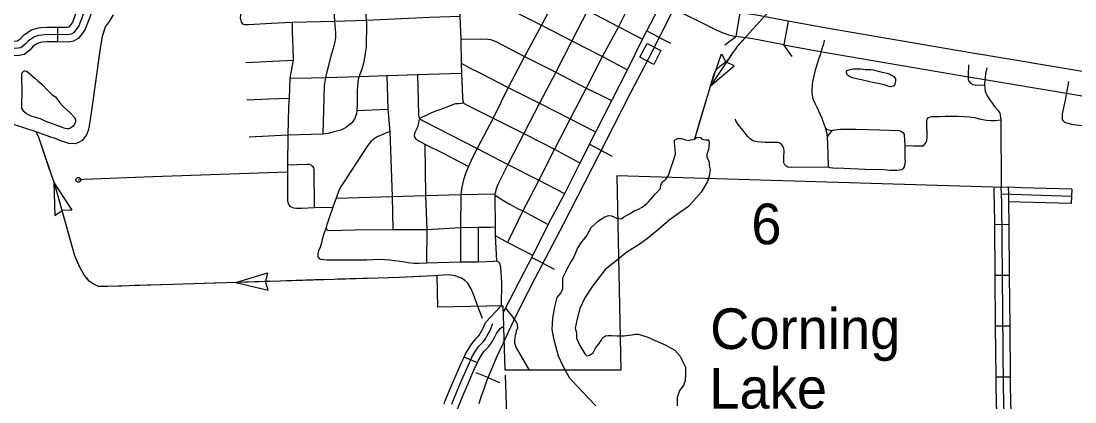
# Model space of a CAD drawing. Extents: x 1164457 to 1439835, y 1590918 to 1773502.
# Drawn here: x 1293538 to 1304504, y 1629674 to 1633633 of the extents above; entities that cross this region are included whole.
import ezdxf

# ---------------------------------------------------------------- set-up
doc = ezdxf.new("R2010")
doc.units = 0
for name, color, linetype in [('Level 10', 7, 'Continuous'), ('Level 15', 7, 'Continuous'), ('Level 32', 7, 'Continuous'), ('Level 33', 7, 'Continuous'), ('Level 34', 7, 'Continuous'), ('Level 35', 7, 'Continuous'), ('Level 37', 7, 'Continuous'), ('Level 4', 7, 'Continuous'), ('Level 40', 7, 'Continuous'), ('Level 43', 7, 'Continuous'), ('Level 45', 7, 'Continuous'), ('Level 5', 7, 'Continuous'), ('Level 6', 7, 'Continuous')]:
    doc.layers.add(name, color=color, linetype=linetype)

msp = doc.modelspace()

# ---------------------------------------------------------------- linework, layer by layer
at = {"layer": 'Level 10'}
for points in [[(1306005, 1632861), (1304458, 1633130), (1303607, 1633270), (1303419, 1633303), (1301918, 1633558), (1301522, 1633633), (1301476, 1633387)], [(1301476, 1633387), (1301874, 1633312), (1303377, 1633056), (1303566, 1633024), (1304416, 1632883), (1305965, 1632615)]]:
    msp.add_lwpolyline(points, dxfattribs=at)
at = {"layer": 'Level 15'}
for points in [[(1300195, 1633840), (1300443, 1633703), (1300612, 1633620), (1300765, 1633544), (1300833, 1633513), (1300904, 1633490), (1300944, 1633479), (1300979, 1633472), (1301022, 1633719)], [(1301522, 1633633), (1301192, 1633695), (1301022, 1633719)], [(1301476, 1633387), (1301151, 1633448), (1300979, 1633472)]]:
    msp.add_lwpolyline(points, dxfattribs=at)
at = {"layer": 'Level 32'}
for p, q in [((1293917, 1633566), (1293916, 1633416)), ((1303820, 1631517), (1303670, 1631516)), ((1303824, 1630989), (1303675, 1630988)), ((1303829, 1630461), (1303679, 1630460)), ((1298286, 1630081), (1298149, 1630141)), ((1303834, 1629933), (1303684, 1629932))]:
    msp.add_line(p, q, dxfattribs=at)
for points in [[(1294219, 1633889), (1294220, 1633849), (1294217, 1633804), (1294200, 1633746), (1294173, 1633672), (1294139, 1633584), (1294111, 1633544), (1294083, 1633512), (1294058, 1633497), (1294023, 1633490), (1293808, 1633492), (1293753, 1633488), (1293721, 1633482), (1293678, 1633469), (1293616, 1633428), (1293578, 1633388), (1293537, 1633356), (1293508, 1633350), (1293465, 1633347)], [(1294294, 1633832), (1294292, 1633791), (1294272, 1633722), (1294243, 1633645), (1294205, 1633549), (1294170, 1633498), (1294132, 1633453), (1294084, 1633425), (1294030, 1633415), (1293916, 1633416)], [(1294144, 1633839), (1294143, 1633816), (1294129, 1633770), (1294103, 1633698), (1294072, 1633619), (1294051, 1633589), (1294035, 1633570), (1294031, 1633568), (1294017, 1633565), (1293917, 1633566)], [(1293917, 1633566), (1293806, 1633567), (1293743, 1633563), (1293703, 1633555), (1293646, 1633538), (1293568, 1633486), (1293527, 1633443), (1293505, 1633426), (1293498, 1633424), (1293401, 1633419)], [(1293916, 1633416), (1293811, 1633417), (1293763, 1633414), (1293739, 1633409), (1293710, 1633400), (1293665, 1633371), (1293629, 1633332), (1293570, 1633286), (1293517, 1633275), (1293405, 1633269)], [(1303670, 1631516), (1303667, 1631741), (1303665, 1631831), (1303663, 1631910), (1303813, 1631905)], [(1303916, 1623599), (1303905, 1623926), (1303843, 1626289), (1303808, 1627880), (1303774, 1629219), (1303760, 1629836), (1303742, 1631743), (1303740, 1631833), (1303738, 1631903)], [(1303820, 1631517), (1303817, 1631744), (1303815, 1631835), (1303813, 1631905)], [(1303675, 1630988), (1303670, 1631516)], [(1303824, 1630989), (1303820, 1631517)], [(1303679, 1630460), (1303675, 1630988)], [(1303829, 1630461), (1303824, 1630989)], [(1298149, 1630141), (1298163, 1630173), (1298197, 1630230), (1298218, 1630264), (1298241, 1630297), (1298271, 1630330), (1298292, 1630350), (1298309, 1630371), (1298320, 1630392), (1298334, 1630416), (1298350, 1630448), (1298370, 1630500), (1298535, 1630674), (1298552, 1630674), (1298559, 1630463)], [(1298020, 1629652), (1298044, 1629714), (1298070, 1629772), (1298112, 1629872), (1298183, 1630037), (1298204, 1630081), (1298229, 1630138), (1298261, 1630191), (1298280, 1630223), (1298299, 1630250), (1298325, 1630277), (1298348, 1630299), (1298372, 1630330), (1298386, 1630356), (1298400, 1630381), (1298419, 1630417), (1298439, 1630472), (1298448, 1630491)], [(1298286, 1630081), (1298296, 1630103), (1298325, 1630152), (1298343, 1630182), (1298358, 1630202), (1298378, 1630224), (1298403, 1630248), (1298435, 1630288), (1298452, 1630320), (1298466, 1630345), (1298487, 1630387), (1298523, 1630436), (1298559, 1630463)], [(1303684, 1629932), (1303679, 1630460)], [(1303834, 1629933), (1303829, 1630461)], [(1297940, 1629650), (1297949, 1629678), (1297975, 1629743), (1298001, 1629802), (1298043, 1629902), (1298114, 1630068), (1298136, 1630113), (1298149, 1630141)], [(1298081, 1629600), (1298090, 1629625), (1298113, 1629685), (1298139, 1629743), (1298181, 1629843), (1298251, 1630006), (1298272, 1630050), (1298286, 1630081)], [(1303695, 1629403), (1303685, 1629835), (1303684, 1629932)], [(1303845, 1629406), (1303835, 1629838), (1303834, 1629933)]]:
    msp.add_lwpolyline(points, dxfattribs=at)
at = {"layer": 'Level 33'}
for points in [[(1295770, 1634927), (1295807, 1633943), (1295820, 1633696), (1295819, 1633662), (1295827, 1633621), (1295841, 1633603), (1295859, 1633596), (1295904, 1633596), (1296143, 1633610), (1296360, 1633623), (1296801, 1633632), (1297128, 1633643), (1297791, 1633674), (1298105, 1633685)], [(1298064, 1634956), (1298072, 1634666), (1298083, 1634355), (1298093, 1634048), (1298105, 1633685), (1298114, 1633445), (1298118, 1633194), (1298120, 1633092), (1298130, 1632838), (1298131, 1632821), (1298141, 1632783), (1298148, 1632776), (1298179, 1632758), (1298216, 1632742), (1298451, 1632625), (1298770, 1632465), (1299090, 1632301), (1299242, 1632217), (1299353, 1632159)], [(1298412, 1634687), (1298406, 1634658), (1298402, 1634623), (1298418, 1634366), (1298419, 1634275), (1298426, 1634065), (1298430, 1633921), (1298435, 1633880), (1298450, 1633860), (1298476, 1633836), (1298490, 1633826), (1298626, 1633753), (1298952, 1633589), (1299268, 1633426), (1299587, 1633263), (1299849, 1633127)], [(1298419, 1634275), (1298796, 1634078), (1299121, 1633908), (1299432, 1633742), (1299757, 1633573), (1300003, 1633444)], [(1296780, 1633996), (1296801, 1633632), (1296811, 1633507), (1296811, 1633462), (1296804, 1633420), (1296786, 1633347), (1296766, 1633283), (1296712, 1633076), (1296707, 1633045), (1296693, 1632964), (1296677, 1632458)], [(1299121, 1633908), (1298952, 1633589), (1298776, 1633263), (1298607, 1632943), (1298451, 1632625), (1298284, 1632307), (1298249, 1632244), (1298221, 1632185), (1298193, 1632121), (1298173, 1632074), (1298156, 1632026), (1298139, 1631968), (1298131, 1631937), (1298124, 1631906), (1298119, 1631861), (1298116, 1631830), (1298112, 1631487), (1298111, 1631129)], [(1300207, 1633834), (1300004, 1633447), (1299850, 1633130), (1299685, 1632810), (1299519, 1632486), (1299360, 1632171), (1299355, 1632163), (1299195, 1631844), (1299024, 1631523), (1298863, 1631201), (1298720, 1630926), (1298555, 1630604)], [(1299873, 1633809), (1299830, 1633725), (1299760, 1633580), (1299590, 1633269), (1299421, 1632944), (1299255, 1632622), (1299093, 1632308), (1298930, 1631986), (1298823, 1631779), (1298764, 1631666), (1298605, 1631338)], [(1297123, 1633729), (1297134, 1633611), (1297128, 1633360), (1297124, 1633319), (1297116, 1633273), (1297102, 1633196), (1297086, 1633145), (1297074, 1633105), (1297061, 1633071), (1297055, 1633057), (1297049, 1633038), (1297043, 1633001), (1297039, 1632951), (1297035, 1632916), (1297035, 1632768), (1297032, 1632705), (1297027, 1632669), (1297020, 1632644), (1297012, 1632619), (1296991, 1632588), (1296972, 1632568), (1296950, 1632550), (1296924, 1632530), (1296900, 1632517), (1296854, 1632496), (1296794, 1632480), (1296733, 1632466), (1296677, 1632458), (1296313, 1632447), (1295911, 1632427)], [(1299432, 1633742), (1299268, 1633426), (1299102, 1633102), (1298933, 1632781), (1298770, 1632465), (1298604, 1632143), (1298541, 1632016), (1298510, 1631955), (1298493, 1631917), (1298479, 1631879), (1298475, 1631854), (1298468, 1631836), (1298468, 1631824), (1298468, 1631812), (1298472, 1631495), (1298473, 1631404), (1298486, 1631140)], [(1296360, 1633623), (1296360, 1633526), (1296364, 1633429), (1296365, 1633357), (1296370, 1633227), (1296336, 1633041), (1296328, 1632830), (1296321, 1632740), (1296313, 1632447), (1296311, 1632138), (1296312, 1632067), (1296309, 1631813), (1296310, 1631799), (1296311, 1631765), (1296314, 1631749), (1296321, 1631726), (1296337, 1631707), (1296357, 1631697), (1296373, 1631693), (1296405, 1631688), (1296459, 1631689), (1296589, 1631696), (1296782, 1631697)], [(1298114, 1633445), (1298317, 1633447), (1298394, 1633445), (1298423, 1633442), (1298477, 1633419), (1298776, 1633263), (1299102, 1633102), (1299418, 1632937), (1299571, 1632864), (1299683, 1632806)], [(1301896, 1633435), (1301887, 1633393), (1301875, 1633354), (1301862, 1633319), (1301856, 1633291), (1301837, 1633234), (1301803, 1633121), (1301775, 1633000), (1301769, 1632975), (1301766, 1632912), (1301768, 1632882), (1301774, 1632841), (1301780, 1632819), (1301797, 1632778), (1301817, 1632738), (1301870, 1632624), (1301896, 1632556), (1301907, 1632525), (1301920, 1632480), (1301925, 1632428), (1301930, 1632349), (1301935, 1632133), (1301939, 1632114)], [(1295878, 1633201), (1296370, 1633227)], [(1298118, 1633194), (1298205, 1633148), (1298304, 1633099), (1298607, 1632943), (1298933, 1632781), (1299252, 1632615), (1299517, 1632481)], [(1303398, 1633179), (1303393, 1633067), (1303394, 1633027), (1303400, 1633007), (1303416, 1632988), (1303441, 1632975), (1303466, 1632970), (1303563, 1632968)], [(1303587, 1633147), (1303575, 1633087), (1303569, 1633040), (1303566, 1633011), (1303563, 1632986), (1303563, 1632968), (1303565, 1632938), (1303571, 1632903), (1303588, 1632861), (1303591, 1632857)], [(1296336, 1633041), (1296556, 1633042), (1296707, 1633045), (1297055, 1633057), (1297344, 1633067), (1297664, 1633078), (1298120, 1633092)], [(1297344, 1633067), (1297356, 1632716), (1297376, 1632486), (1297401, 1631810), (1297406, 1631468)], [(1297664, 1633078), (1297674, 1632659), (1297678, 1632633), (1297687, 1632621), (1297693, 1632614), (1297721, 1632597), (1297857, 1632526), (1298284, 1632307), (1298604, 1632143), (1298927, 1631979), (1299193, 1631840)], [(1295888, 1632815), (1296114, 1632824), (1296328, 1632830)], [(1297032, 1632705), (1297356, 1632716)], [(1297687, 1632621), (1297678, 1632596), (1297673, 1632574), (1297662, 1632530), (1297644, 1632490), (1297632, 1632462), (1297629, 1632447), (1297630, 1632434), (1297634, 1632421), (1297647, 1632405), (1297738, 1632353), (1297936, 1632256), (1298193, 1632121)], [(1297376, 1632486), (1297243, 1632431), (1297202, 1632403), (1297178, 1632380), (1297144, 1632335), (1296966, 1632065), (1296934, 1632017), (1296904, 1631968), (1296870, 1631918), (1296846, 1631872), (1296817, 1631792), (1296782, 1631697)], [(1301907, 1632525), (1301921, 1632510), (1301941, 1632501), (1301970, 1632497), (1301992, 1632498), (1301968, 1632485), (1301950, 1632466), (1301936, 1632448), (1301925, 1632428)], [(1301992, 1632498), (1302033, 1632506), (1302064, 1632508), (1302225, 1632508), (1302471, 1632501), (1302671, 1632494), (1302693, 1632489), (1302715, 1632473), (1302728, 1632456), (1302728, 1632449)], [(1297738, 1632353), (1297747, 1631821), (1297759, 1631467), (1297756, 1631121)], [(1296311, 1632138), (1296517, 1632146), (1296536, 1632144), (1296552, 1632138), (1296561, 1632133), (1296572, 1632124), (1296582, 1632109), (1296585, 1632087), (1296589, 1631696)], [(1294134, 1631983), (1294191, 1631991), (1294910, 1632019), (1296312, 1632067)], [(1296817, 1631792), (1297401, 1631810), (1297747, 1631821), (1298116, 1631830), (1298468, 1631836)], [(1298468, 1631824), (1298482, 1631815), (1298541, 1631777), (1298577, 1631757), (1298617, 1631733), (1298657, 1631711), (1298704, 1631686), (1298761, 1631660), (1299022, 1631520)], [(1296782, 1631697), (1296741, 1631578), (1296726, 1631535), (1296721, 1631518), (1296712, 1631487), (1296715, 1631470), (1296728, 1631459), (1296739, 1631457), (1297008, 1631464)], [(1297008, 1631464), (1297406, 1631468), (1297759, 1631467), (1298112, 1631487)], [(1298112, 1631487), (1298296, 1631489), (1298428, 1631491), (1298472, 1631495)], [(1298473, 1631404), (1298602, 1631332), (1298861, 1631198)]]:
    msp.add_lwpolyline(points, dxfattribs=at)
msp.add_circle((1294134, 1631983), 25, dxfattribs=at)
at = {"layer": 'Level 34'}
for points in [[(1304437, 1633006), (1304402, 1632810), (1304372, 1632667), (1304370, 1632635), (1304372, 1632611), (1304378, 1632598), (1304388, 1632588), (1304397, 1632582), (1304417, 1632574), (1304434, 1632571), (1304468, 1632563), (1304544, 1632552), (1304578, 1632548), (1304613, 1632542), (1304641, 1632535), (1304990, 1632479), (1305922, 1632319)], [(1303591, 1632857), (1303623, 1632809), (1303641, 1632787), (1303669, 1632744), (1303702, 1632706)], [(1298141, 1632783), (1298130, 1632779), (1298117, 1632776), (1298093, 1632774), (1298064, 1632771), (1298046, 1632768), (1298020, 1632759), (1297977, 1632742), (1297907, 1632715), (1297850, 1632695), (1297802, 1632674), (1297759, 1632655), (1297712, 1632635), (1297687, 1632621)], [(1303702, 1632706), (1303722, 1632676), (1303727, 1632656), (1303733, 1632606), (1303738, 1631908)], [(1302098, 1632101), (1301984, 1632105), (1301958, 1632107), (1301939, 1632114), (1301556, 1632111), (1301518, 1632114), (1301500, 1632123), (1301486, 1632137), (1301478, 1632153), (1301476, 1632161), (1301475, 1632174), (1301476, 1632217), (1301479, 1632281), (1301475, 1632310), (1301465, 1632333), (1301454, 1632345), (1301434, 1632363), (1301416, 1632369), (1301399, 1632372), (1301282, 1632369), (1301198, 1632376), (1301162, 1632385), (1301127, 1632406), (1301101, 1632434), (1301083, 1632454), (1301064, 1632483), (1301036, 1632515), (1300999, 1632557), (1300977, 1632597), (1300972, 1632613)], [(1302733, 1632339), (1302827, 1632336), (1302906, 1632335), (1302923, 1632336), (1302939, 1632349), (1302958, 1632375), (1302962, 1632388), (1302966, 1632427), (1302962, 1632588), (1302968, 1632613), (1302979, 1632629), (1302997, 1632637), (1303016, 1632640), (1303094, 1632640), (1303155, 1632645), (1303246, 1632646), (1303287, 1632645), (1303356, 1632642), (1303408, 1632636), (1303459, 1632629), (1303524, 1632613), (1303584, 1632604), (1303627, 1632600), (1303675, 1632601), (1303733, 1632606)], [(1302728, 1632449), (1302733, 1632339), (1302736, 1632209), (1302739, 1632178), (1302735, 1632153), (1302728, 1632119), (1302717, 1632100), (1302704, 1632088), (1302656, 1632078), (1302582, 1632079), (1302511, 1632085), (1302323, 1632091)], [(1302323, 1632091), (1302099, 1632101)], [(1296712, 1631487), (1296688, 1631421), (1296673, 1631363), (1296664, 1631328), (1296650, 1631284), (1296633, 1631246), (1296625, 1631214), (1296627, 1631184), (1296643, 1631163), (1296657, 1631158), (1296719, 1631151), (1296813, 1631152), (1297133, 1631152), (1297263, 1631157), (1297376, 1631152), (1297481, 1631139), (1297511, 1631135)], [(1298296, 1631489), (1298296, 1631202), (1298294, 1631132)], [(1297511, 1631135), (1297565, 1631123), (1297626, 1631116), (1297680, 1631117), (1297756, 1631121), (1298111, 1631129), (1298294, 1631132), (1298457, 1631139), (1298486, 1631140), (1298501, 1631134), (1298510, 1631125), (1298513, 1631122), (1298520, 1631106), (1298526, 1631070), (1298536, 1630915), (1298535, 1630674)], [(1298578, 1630648), (1298651, 1630557), (1298667, 1630537), (1298683, 1630517), (1298696, 1630494), (1298701, 1630471), (1298703, 1630440), (1298691, 1630409), (1298675, 1630343), (1298672, 1630307), (1298673, 1630287), (1298680, 1630266), (1298691, 1630237), (1298827, 1630005)]]:
    msp.add_lwpolyline(points, dxfattribs=at)
at = {"layer": 'Level 35'}
for points in [[(1302371, 1633002), (1302285, 1633022), (1302230, 1633032), (1302190, 1633042), (1302159, 1633057), (1302137, 1633071), (1302130, 1633088), (1302127, 1633097), (1302127, 1633108), (1302135, 1633120), (1302155, 1633127), (1302196, 1633138), (1302242, 1633138), (1302280, 1633138), (1302322, 1633128), (1302362, 1633128), (1302385, 1633128), (1302405, 1633127)], [(1302405, 1633127), (1302485, 1633105), (1302547, 1633092), (1302579, 1633080), (1302597, 1633072), (1302620, 1633057), (1302638, 1633034), (1302638, 1633011), (1302631, 1632978), (1302615, 1632955), (1302585, 1632951), (1302581, 1632951), (1302557, 1632956), (1302521, 1632971), (1302456, 1632985), (1302431, 1632989), (1302371, 1633002)], [(1293549, 1632889), (1293545, 1633059), (1293548, 1633093), (1293562, 1633108), (1293570, 1633116), (1293581, 1633116), (1293597, 1633113), (1293681, 1633041), (1293715, 1633007), (1293755, 1632977), (1293820, 1632908)], [(1293820, 1632908), (1293863, 1632865), (1293895, 1632845), (1293941, 1632782), (1293984, 1632737), (1294050, 1632679), (1294095, 1632631), (1294104, 1632607), (1294104, 1632584), (1294095, 1632561), (1294081, 1632539), (1294054, 1632520), (1294033, 1632513), (1294014, 1632513), (1293998, 1632516), (1293958, 1632530), (1293790, 1632593)], [(1293790, 1632593), (1293742, 1632615), (1293688, 1632632), (1293642, 1632646), (1293594, 1632669), (1293566, 1632693), (1293548, 1632728), (1293546, 1632769), (1293549, 1632889)], [(1300064, 1631751), (1300141, 1631837), (1300191, 1631893), (1300194, 1631930), (1300213, 1631962), (1300247, 1631990), (1300272, 1632020), (1300295, 1632094), (1300330, 1632195), (1300349, 1632252), (1300343, 1632307), (1300338, 1632364), (1300339, 1632394), (1300370, 1632413), (1300414, 1632414), (1300452, 1632397), (1300490, 1632391), (1300509, 1632398), (1300544, 1632405), (1300566, 1632424), (1300582, 1632427), (1300607, 1632423), (1300623, 1632405), (1300659, 1632398), (1300687, 1632398), (1300695, 1632389), (1300700, 1632364), (1300693, 1632299), (1300674, 1632247), (1300674, 1632222), (1300697, 1632167), (1300700, 1632132), (1300709, 1632089), (1300699, 1632022), (1300681, 1631966), (1300614, 1631856), (1300482, 1631706), (1300402, 1631650)], [(1299518, 1629635), (1299441, 1629715), (1299320, 1629840), (1299245, 1629926), (1299179, 1630047), (1299132, 1630151), (1299102, 1630253), (1299086, 1630318), (1299066, 1630428), (1299070, 1630544), (1299093, 1630664), (1299118, 1630759), (1299154, 1630805), (1299175, 1630850), (1299175, 1630887), (1299175, 1630921), (1299175, 1630964), (1299207, 1631025), (1299227, 1631073), (1299257, 1631121), (1299288, 1631168), (1299329, 1631269), (1299372, 1631337), (1299411, 1631382), (1299427, 1631403), (1299443, 1631434), (1299470, 1631487), (1299543, 1631552), (1299568, 1631571), (1299611, 1631599), (1299652, 1631613), (1299682, 1631610), (1299736, 1631585), (1299784, 1631578), (1299807, 1631594), (1299870, 1631628), (1299918, 1631659), (1299957, 1631675), (1300002, 1631700), (1300045, 1631732), (1300064, 1631751)], [(1300402, 1631650), (1300283, 1631562), (1300174, 1631471), (1300055, 1631373), (1299969, 1631312), (1299842, 1631230), (1299726, 1631139), (1299617, 1631050), (1299537, 1630948), (1299476, 1630866), (1299403, 1630757), (1299351, 1630645), (1299324, 1630539), (1299303, 1630441), (1299317, 1630391), (1299317, 1630336), (1299351, 1630259), (1299403, 1630173), (1299424, 1630152), (1299453, 1630159), (1299490, 1630186), (1299517, 1630232), (1299555, 1630280), (1299576, 1630311), (1299590, 1630339), (1299619, 1630361), (1299646, 1630366), (1299683, 1630366), (1299742, 1630361), (1299810, 1630361), (1299866, 1630369), (1299896, 1630371), (1299926, 1630380), (1299962, 1630380), (1299984, 1630373), (1300060, 1630346), (1300135, 1630311), (1300242, 1630266), (1300342, 1630211), (1300396, 1630150), (1300426, 1630091), (1300453, 1630034), (1300453, 1629964), (1300449, 1629896), (1300430, 1629844), (1300390, 1629794), (1300367, 1629721), (1300367, 1629635)]]:
    msp.add_lwpolyline(points, dxfattribs=at)
at = {"layer": 'Level 37'}
for points in [[(1300981, 1633472), (1300860, 1633384)], [(1301561, 1633263), (1301476, 1633387)]]:
    msp.add_lwpolyline(points, dxfattribs=at)
at = {"layer": 'Level 4'}
msp.add_lwpolyline([(1298577, 1629954), (1298587, 1629651), (1298598, 1629367), (1298628, 1628587)], dxfattribs=at)
at = {"layer": 'Level 40'}
for p, q in [((1300177, 1633463), (1300059, 1633523)), ((1300177, 1633463), (1300295, 1633403)), ((1299573, 1632289), (1299456, 1632350)), ((1299573, 1632289), (1299690, 1632229)), ((1298968, 1631116), (1298851, 1631177)), ((1298968, 1631116), (1299085, 1631055)), ((1298395, 1629927), (1298274, 1629978)), ((1298395, 1629927), (1298517, 1629876))]:
    msp.add_line(p, q, dxfattribs=at)
for points in [[(1300340, 1633776), (1300318, 1633735), (1300191, 1633491), (1300062, 1633237), (1299881, 1632886), (1299702, 1632540), (1299476, 1632102), (1299181, 1631526), (1298886, 1630957)], [(1300318, 1633735), (1300191, 1633491), (1300062, 1633237), (1299881, 1632886), (1299702, 1632540), (1299476, 1632102), (1299181, 1631526), (1298886, 1630957), (1298739, 1630673), (1298663, 1630516), (1298608, 1630400), (1298551, 1630279), (1298490, 1630147), (1298432, 1630015), (1298384, 1629899), (1298352, 1629807), (1298327, 1629734), (1298302, 1629655)], [(1298886, 1630957), (1298739, 1630673), (1298663, 1630516), (1298608, 1630400), (1298551, 1630279), (1298490, 1630147), (1298432, 1630015), (1298384, 1629899), (1298352, 1629807), (1298327, 1629734), (1298302, 1629655)]]:
    msp.add_lwpolyline(points, dxfattribs=at)
msp.add_lwpolyline([(1300052, 1633401), (1300197, 1633326), (1300122, 1633181), (1299977, 1633256)], close=True, dxfattribs=at)
at = {"layer": 'Level 43'}
for p, q in [((1300711, 1632960), (1300825, 1633292)), ((1300825, 1633292), (1300869, 1633211)), ((1300711, 1632960), (1300958, 1633168)), ((1300958, 1633168), (1300870, 1633210)), ((1293881, 1631956), (1293891, 1631613)), ((1293881, 1631956), (1294065, 1631666)), ((1293891, 1631613), (1293967, 1631664)), ((1294065, 1631666), (1293967, 1631664)), ((1295774, 1630916), (1296103, 1631015)), ((1296103, 1631015), (1296082, 1630926)), ((1296108, 1630837), (1296082, 1630925)), ((1295774, 1630916), (1296108, 1630837))]:
    msp.add_line(p, q, dxfattribs=at)
for points in [[(1302696, 1634805), (1302384, 1634765), (1302296, 1634755), (1302243, 1634742), (1302215, 1634733), (1302195, 1634726), (1302142, 1634702), (1302097, 1634666), (1302051, 1634608), (1301853, 1634360), (1301746, 1634245), (1301302, 1633719), (1301287, 1633699), (1300983, 1633360), (1300983, 1633357), (1300970, 1633339), (1300951, 1633317), (1300898, 1633238), (1300846, 1633189), (1300808, 1633161), (1300769, 1633123), (1300753, 1633100), (1300737, 1633048), (1300544, 1632405)], [(1294498, 1633696), (1294454, 1633628), (1294414, 1633572), (1294382, 1633471), (1294366, 1633373), (1294284, 1632801), (1294268, 1632678), (1294248, 1632544), (1294238, 1632494), (1294218, 1632452), (1294173, 1632392), (1294137, 1632369), (1294106, 1632357), (1294035, 1632361), (1293974, 1632382), (1293941, 1632392), (1293903, 1632409), (1293837, 1632431), (1293697, 1632481), (1293459, 1632558)], [(1294405, 1633545), (1294382, 1633471), (1294366, 1633373), (1294363, 1633352)], [(1301072, 1633459), (1301004, 1633383)], [(1294363, 1633352), (1294335, 1633156)], [(1300925, 1633278), (1300898, 1633238), (1300711, 1632960)], [(1294316, 1633025), (1294284, 1632801), (1294268, 1632678), (1294261, 1632633)], [(1300673, 1632834), (1300616, 1632644)], [(1300616, 1632644), (1300558, 1632454)], [(1293799, 1632444), (1293697, 1632481), (1293459, 1632558), (1293422, 1632566)], [(1298340, 1630540), (1298308, 1630622), (1298271, 1630726), (1298254, 1630773), (1298221, 1630851), (1298188, 1630910), (1298157, 1630938), (1298121, 1630960), (1298090, 1630972), (1298055, 1630985), (1297989, 1630994), (1297931, 1630992), (1297840, 1630986), (1297475, 1630969), (1294437, 1630874), (1294343, 1630874), (1294288, 1630901), (1294248, 1630931), (1294193, 1631000), (1294154, 1631067), (1294097, 1631194), (1293892, 1631924), (1293722, 1632424), (1293697, 1632481)], [(1293839, 1632081), (1293722, 1632424), (1293697, 1632481)], [(1294240, 1632503), (1294238, 1632494), (1294218, 1632452), (1294173, 1632392), (1294137, 1632369), (1294106, 1632357), (1294035, 1632361), (1293974, 1632382), (1293941, 1632392), (1293923, 1632400)], [(1293990, 1631575), (1293892, 1631924), (1293881, 1631956)], [(1294151, 1631073), (1294097, 1631194), (1294026, 1631448)], [(1294587, 1630879), (1294437, 1630874), (1294343, 1630874), (1294288, 1630901), (1294248, 1630931), (1294223, 1630963)], [(1296170, 1630928), (1295774, 1630916)], [(1296698, 1630945), (1296302, 1630932)], [(1297226, 1630961), (1296830, 1630949)], [(1297753, 1630982), (1297475, 1630969), (1297357, 1630965)], [(1298223, 1630848), (1298221, 1630851), (1298188, 1630910), (1298157, 1630938), (1298121, 1630960), (1298090, 1630972), (1298055, 1630985), (1297989, 1630994), (1297931, 1630992), (1297885, 1630989)], [(1295115, 1630895), (1294719, 1630883)], [(1295444, 1630906), (1295247, 1630899)], [(1295642, 1630912), (1295444, 1630906)], [(1298340, 1630540), (1298308, 1630622), (1298271, 1630726)]]:
    msp.add_lwpolyline(points, dxfattribs=at)
at = {"layer": 'Level 45'}
msp.add_line((1304471, 1631885), (1304466, 1631735), dxfattribs=at)
for points in [[(1304469, 1631810), (1303740, 1631833)], [(1303943, 1631901), (1303813, 1631905)], [(1304471, 1631885), (1303943, 1631901)], [(1303938, 1631751), (1303817, 1631755)], [(1304466, 1631735), (1303938, 1631751)]]:
    msp.add_lwpolyline(points, dxfattribs=at)
at = {"layer": 'Level 6'}
for points in [[(1303649, 1631906), (1299736, 1632023), (1299779, 1630005), (1298575, 1630005)], [(1298552, 1630674), (1297875, 1630658), (1297868, 1630990)], [(1298575, 1630005), (1298560, 1630453)]]:
    msp.add_lwpolyline(points, dxfattribs=at)

# ---------------------------------------------------------------- texts
at = {"layer": 'Level 35'}
for s, p in [('Corning', (1300709, 1630224)), ('Lake', (1300700, 1629605))]:
    msp.add_text(s, height=422.4, dxfattribs=at).set_placement(p)
at = {"layer": 'Level 5'}
msp.add_text('6', height=422, dxfattribs=at).set_placement((1301137, 1631313))

doc.saveas('drawing.dxf')
